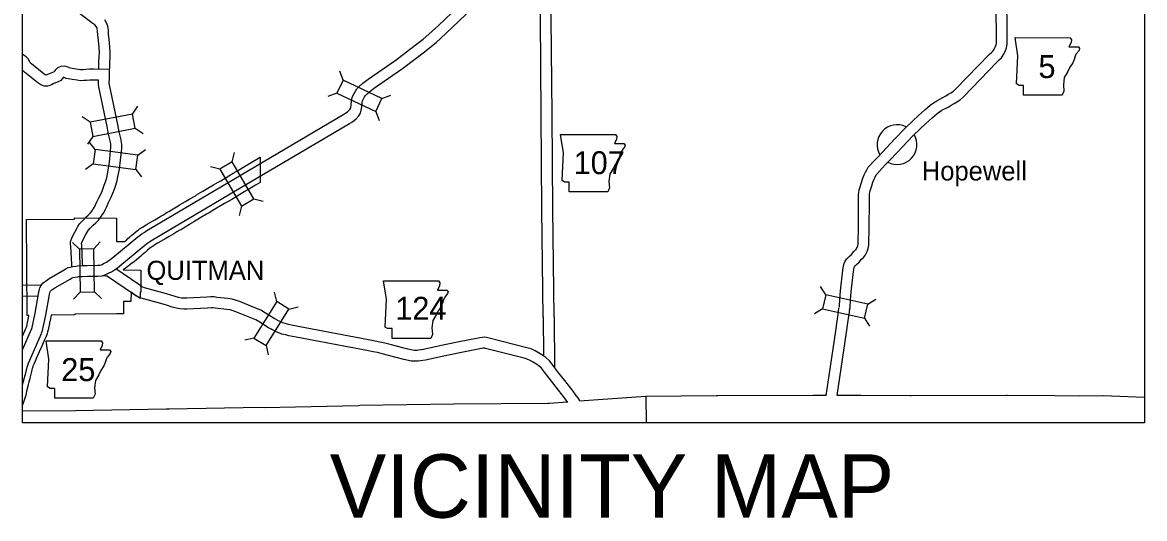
# Model space of a CAD drawing. Extents: x 1212896 to 1368412, y 378476 to 478763.
# Drawn here: x 1215273 to 1246287, y 442963 to 456675 of the extents above; entities that cross this region are included whole.
import ezdxf

# ---------------------------------------------------------------- set-up
doc = ezdxf.new("R2010")
doc.units = 0
for name, color, linetype in [('1', 7, 'Continuous'), ('2', 7, 'Continuous'), ('Level 10', 7, 'Continuous'), ('Level 11', 7, 'Continuous'), ('Level 2', 7, 'Continuous'), ('Level 20', 7, 'Continuous'), ('Level 21', 7, 'Continuous'), ('Level 24', 7, 'Continuous'), ('Level 6', 7, 'Continuous')]:
    doc.layers.add(name, color=color, linetype=linetype)

msp = doc.modelspace()

# ---------------------------------------------------------------- linework, layer by layer
at = {"layer": '1'}
msp.add_lwpolyline([(1215273, 477661), (1246287, 477661), (1246287, 445613), (1215273, 445613)], close=True, dxfattribs=at)
at = {"layer": 'Level 10'}
for points in [[(1237843, 448801), (1237852, 448843), (1237864, 449022), (1237881, 449261), (1237943, 449828), (1237954, 449896), (1237962, 449951), (1237983, 450013), (1238012, 450075), (1238058, 450141), (1238118, 450203), (1238184, 450264), (1238253, 450340), (1238302, 450386), (1238317, 450403), (1238329, 450423), (1238343, 450456), (1238358, 450499), (1238367, 450551), (1238378, 451043), (1238381, 451679), (1238382, 451902), (1238387, 451972), (1238400, 452047), (1238419, 452107), (1238461, 452252), (1238500, 452369), (1238540, 452465), (1238574, 452535), (1238610, 452605), (1238652, 452675), (1238820, 452858), (1238925, 452963), (1239047, 453092), (1239389, 453455), (1239657, 453739), (1239887, 453962), (1240034, 454092), (1240133, 454184), (1240215, 454259), (1240285, 454321), (1240363, 454388), (1240452, 454456), (1240541, 454508), (1240709, 454599), (1240796, 454650), (1240870, 454690), (1240936, 454732), (1241003, 454777), (1241081, 454846), (1241991, 455788), (1242062, 455855), (1242100, 455893), (1242132, 455939), (1242160, 455996), (1242183, 456055), (1242193, 456103), (1242193, 456181), (1242168, 459007)], [(1238135, 448735), (1238150, 448800), (1238163, 449001), (1238180, 449234), (1238240, 449788), (1238250, 449849), (1238255, 449880), (1238262, 449902), (1238272, 449925), (1238289, 449949), (1238328, 449988), (1238397, 450053), (1238467, 450129), (1238516, 450176), (1238560, 450225), (1238597, 450286), (1238623, 450347), (1238650, 450425), (1238666, 450522), (1238678, 451039), (1238681, 451677), (1238682, 451892), (1238685, 451936), (1238692, 451976), (1238706, 452021), (1238748, 452163), (1238781, 452264), (1238814, 452341), (1238842, 452401), (1238872, 452459), (1238894, 452495), (1239037, 452651), (1239140, 452754), (1239265, 452885), (1239607, 453249), (1239871, 453529), (1240091, 453742), (1240236, 453870), (1240337, 453964), (1240415, 454036), (1240482, 454095), (1240552, 454155), (1240619, 454206), (1240688, 454247), (1240856, 454337), (1240944, 454388), (1241023, 454432), (1241099, 454481), (1241187, 454539), (1241289, 454630), (1242202, 455574), (1242271, 455639), (1242332, 455700), (1242390, 455786), (1242435, 455875), (1242471, 455969), (1242494, 456071), (1242493, 456183), (1242467, 459015)], [(1215520, 448185), (1215540, 448241), (1215621, 448639), (1215730, 449216), (1215740, 449268), (1215755, 449341), (1215803, 449425), (1215848, 449474), (1215901, 449519), (1216012, 449596), (1216430, 449835), (1216473, 449866), (1216533, 449898), (1216596, 449915), (1216670, 449931), (1216746, 449940), (1216792, 449952), (1216915, 449954), (1217059, 449960), (1217348, 449966), (1217423, 449971), (1217454, 449979), (1217489, 449994), (1217536, 450018), (1217581, 450041), (1217651, 450086), (1217702, 450123), (1217769, 450181), (1218464, 450749), (1218526, 450800), (1218576, 450831), (1218633, 450869), (1218715, 450921), (1221112, 452344), (1224160, 454143), (1224215, 454175), (1224256, 454203), (1224288, 454230), (1224325, 454271), (1224338, 454292), (1224347, 454322), (1224358, 454381), (1224367, 454539), (1224400, 454625), (1224441, 454713), (1224474, 454773), (1224519, 454840), (1224588, 454918), (1224677, 454994), (1224832, 455111), (1225599, 455644), (1225971, 455924), (1226204, 456101), (1226345, 456216), (1226508, 456350), (1226770, 456592), (1227504, 457284)], [(1215803, 448085), (1215829, 448160), (1215916, 448581), (1216024, 449158), (1216034, 449208), (1216040, 449234), (1216047, 449247), (1216056, 449258), (1216084, 449281), (1216172, 449341), (1216591, 449582), (1216630, 449610), (1216645, 449618), (1216668, 449624), (1216719, 449635), (1216801, 449644), (1216833, 449652), (1216924, 449655), (1217067, 449660), (1217361, 449666), (1217473, 449673), (1217553, 449695), (1217617, 449723), (1217673, 449751), (1217731, 449781), (1217821, 449838), (1217888, 449888), (1217961, 449950), (1218654, 450516), (1218703, 450556), (1218740, 450581), (1218796, 450618), (1218872, 450666), (1221265, 452086), (1224311, 453884), (1224375, 453921), (1224438, 453963), (1224498, 454014), (1224566, 454090), (1224613, 454167), (1224639, 454250), (1224656, 454345), (1224664, 454475), (1224676, 454508), (1224709, 454578), (1224731, 454617), (1224757, 454656), (1224799, 454704), (1224865, 454761), (1225008, 454868), (1225775, 455401), (1226152, 455685), (1226390, 455866), (1226535, 455984), (1226705, 456124), (1226974, 456372), (1227711, 457067)], [(1217384, 455383), (1217388, 455580), (1217396, 455736), (1217401, 455840), (1217391, 455978), (1217373, 456175), (1217356, 456333), (1217349, 456430), (1217340, 456503), (1217328, 456536), (1217310, 456565), (1217272, 456606), (1217189, 456664), (1216659, 457071)], [(1216942, 449953), (1216933, 450016), (1216911, 450520), (1216905, 450569), (1216904, 450576), (1216905, 450579), (1216912, 450596), (1216931, 450640), (1217037, 450834), (1217064, 450881), (1217092, 450926), (1217149, 450990), (1217232, 451072), (1217301, 451135), (1217378, 451214), (1217434, 451288), (1217478, 451355), (1217520, 451415), (1217562, 451499), (1217607, 451592), (1217653, 451703), (1217728, 451846), (1217770, 451958), (1217814, 452064), (1217857, 452177), (1217894, 452310), (1217940, 452537), (1217954, 452620), (1217964, 452712), (1217974, 452787), (1217984, 452865), (1218008, 453099), (1218016, 453209), (1218022, 453297), (1218013, 453356), (1217999, 453431), (1217946, 453653), (1217927, 453749), (1217906, 453855), (1217683, 454954), (1217674, 455001), (1217673, 455026), (1217679, 455111), (1217681, 455226), (1217688, 455569), (1217696, 455721), (1217701, 455844), (1217690, 456002), (1217672, 456205), (1217654, 456359), (1217648, 456460), (1217633, 456571), (1217601, 456665), (1217549, 456749)], [(1216642, 449927), (1216634, 449989), (1216611, 450495), (1216605, 450547), (1216604, 450608), (1216618, 450666), (1216634, 450709), (1216662, 450773), (1216775, 450980), (1216807, 451035), (1216852, 451107), (1216931, 451196), (1217025, 451290), (1217092, 451351), (1217150, 451410), (1217189, 451461), (1217230, 451523), (1217261, 451569), (1217293, 451631), (1217333, 451714), (1217381, 451830), (1217454, 451969), (1217492, 452069), (1217535, 452174), (1217571, 452271), (1217602, 452380), (1217645, 452591), (1217656, 452660), (1217666, 452748), (1217676, 452826), (1217686, 452901), (1217709, 453125), (1217716, 453230), (1217720, 453286), (1217717, 453307), (1217706, 453368), (1217653, 453589), (1217632, 453692), (1217612, 453797), (1217389, 454896), (1217376, 454965), (1217373, 455028), (1217376, 455082)], [(1215273, 449413), (1215801, 449423), (1215805, 449424)], [(1215273, 449113), (1215709, 449121)], [(1237486, 446362), (1237681, 447650), (1237754, 448151), (1237791, 448420), (1237821, 448599), (1237832, 448689), (1237839, 448780)], [(1237789, 446363), (1237977, 447606), (1238051, 448109), (1238088, 448375), (1238117, 448556), (1238131, 448658), (1238139, 448756)], [(1215273, 447623), (1215524, 448195)], [(1215273, 446656), (1215372, 447032), (1215401, 447144), (1215419, 447202), (1215444, 447261), (1215477, 447340), (1215799, 448075)]]:
    msp.add_lwpolyline(points, dxfattribs=at)
at = {"layer": 'Level 11'}
for points in [[(1229668, 448533), (1229628, 451503), (1229614, 454125), (1229588, 456789), (1229582, 457913), (1229578, 457942)], [(1229968, 448537), (1229928, 451506), (1229914, 454127), (1229888, 456791), (1229882, 457934), (1229873, 458001), (1229863, 458053)], [(1217673, 455377), (1217238, 455384), (1217123, 455380), (1217023, 455373), (1216951, 455369), (1216882, 455366), (1216826, 455372), (1216706, 455393), (1216605, 455413), (1216566, 455420), (1216552, 455425), (1216507, 455447), (1216435, 455465), (1216338, 455461), (1216238, 455421), (1216181, 455355), (1216154, 455316), (1216146, 455312), (1216009, 455252), (1215950, 455228), (1215923, 455215), (1215875, 455249), (1215526, 455527), (1215497, 455553), (1215489, 455563), (1215479, 455586), (1215431, 455670), (1215372, 455723), (1215320, 455758), (1215294, 455780), (1215283, 455792), (1215273, 455807)], [(1217375, 455082), (1217241, 455084), (1217137, 455080), (1217043, 455074), (1216967, 455069), (1216872, 455065), (1216783, 455075), (1216651, 455098), (1216550, 455118), (1216481, 455130), (1216430, 455151), (1216411, 455160), (1216385, 455123), (1216338, 455074), (1216276, 455041), (1216125, 454976), (1216074, 454955), (1216030, 454933), (1215963, 454909), (1215874, 454909), (1215777, 454951), (1215695, 455009), (1215333, 455298), (1215280, 455344), (1215273, 455353)], [(1222365, 448421), (1222229, 448494), (1221992, 448642), (1221860, 448723), (1221653, 448810), (1221278, 448960), (1221166, 449003), (1221072, 449027), (1220952, 449041), (1220642, 449077), (1220573, 449088), (1220482, 449089), (1220372, 449080), (1219815, 449051), (1219751, 449052), (1219669, 449059), (1219588, 449075), (1219490, 449099), (1219376, 449133), (1219254, 449177), (1218645, 449343), (1218601, 449357), (1218563, 449376), (1218488, 449428), (1217851, 449865)], [(1222222, 448157), (1222078, 448235), (1221834, 448387), (1221722, 448456), (1221539, 448532), (1221168, 448681), (1221074, 448717), (1221017, 448732), (1220918, 448743), (1220602, 448780), (1220549, 448788), (1220494, 448788), (1220392, 448780), (1219820, 448751), (1219736, 448752), (1219627, 448761), (1219523, 448782), (1219412, 448809), (1219282, 448848), (1219164, 448891), (1218559, 449055), (1218487, 449078), (1218410, 449117), (1218318, 449181), (1217628, 449654), (1217621, 449658), (1217612, 449661), (1217577, 449667), (1217522, 449672), (1217483, 449672)], [(1229668, 448534), (1229674, 447468)], [(1229968, 448536), (1229976, 447128)], [(1230345, 446173), (1230251, 446304), (1230025, 446592), (1229828, 446848), (1229704, 447007), (1229618, 447119), (1229549, 447183), (1229467, 447240), (1229390, 447288), (1229310, 447330), (1229225, 447368), (1229136, 447396), (1228075, 447666), (1228055, 447669), (1228036, 447672), (1228011, 447670), (1227963, 447664), (1227358, 447547), (1226876, 447444), (1226413, 447343), (1226275, 447321), (1226212, 447313), (1226153, 447309), (1226094, 447309), (1226013, 447317), (1225942, 447332), (1225818, 447362), (1225394, 447470), (1225211, 447518), (1225089, 447549), (1224963, 447575), (1224788, 447604), (1222842, 447976), (1222640, 448013), (1222549, 448037), (1222446, 448064), (1222359, 448094), (1222287, 448125), (1222221, 448157), (1222160, 448194)], [(1230589, 446348), (1230491, 446483), (1230262, 446776), (1230065, 447031), (1229941, 447191), (1229840, 447322), (1229739, 447416), (1229632, 447491), (1229539, 447548), (1229441, 447600), (1229330, 447650), (1229217, 447684), (1228135, 447961), (1228096, 447966), (1228048, 447972), (1227983, 447969), (1227913, 447960), (1227298, 447841), (1226812, 447737), (1226358, 447638), (1226232, 447618), (1226184, 447611), (1226143, 447609), (1226109, 447609), (1226059, 447614), (1226008, 447625), (1225890, 447653), (1225469, 447761), (1225285, 447809), (1225155, 447841), (1225018, 447870), (1224841, 447899), (1222898, 448270), (1222706, 448306), (1222626, 448327), (1222534, 448351), (1222467, 448374), (1222411, 448399), (1222365, 448421), (1222315, 448451)], [(1230682, 446213), (1230673, 446233), (1230641, 446285), (1230599, 446344), (1230564, 446374)]]:
    msp.add_lwpolyline(points, dxfattribs=at)
at = {"layer": 'Level 2'}
for points in [[(1237486, 446362), (1237171, 446361), (1237127, 446361), (1234489, 446356), (1234455, 446352), (1232501, 446341), (1231183, 446246), (1230674, 446207)], [(1232501, 446341), (1232510, 445613)], [(1246287, 446307), (1245146, 446354), (1245137, 446354), (1244476, 446350), (1243807, 446353), (1242485, 446361), (1242461, 446362), (1239833, 446359), (1239805, 446357), (1238444, 446366), (1237789, 446363)], [(1230334, 446181), (1229832, 446140), (1229805, 446141), (1227200, 446129), (1224599, 446084), (1224557, 446083), (1221954, 446028), (1221885, 446029), (1219333, 445986), (1219243, 445983), (1216736, 445937), (1215273, 445929)]]:
    msp.add_lwpolyline(points, dxfattribs=at)
at = {"layer": 'Level 20'}
for p, q in [((1224133, 455080), (1224043, 455328)), ((1224133, 455080), (1223965, 454721)), ((1225208, 454575), (1224133, 455080)), ((1223965, 454721), (1223716, 454631)), ((1223965, 454721), (1225040, 454216)), ((1225208, 454575), (1225457, 454664)), ((1218312, 454142), (1218460, 454361)), ((1225040, 454216), (1225208, 454575)), ((1217146, 453916), (1216927, 454063)), ((1218312, 454142), (1217146, 453916)), ((1218388, 453754), (1218312, 454142)), ((1225040, 454216), (1225130, 453968)), ((1217146, 453916), (1217222, 453527)), ((1217222, 453527), (1218388, 453754)), ((1218388, 453754), (1218607, 453606)), ((1217222, 453527), (1217074, 453308)), ((1217282, 453163), (1217122, 453373)), ((1217282, 453163), (1217230, 452771)), ((1218460, 453007), (1217282, 453163)), ((1218460, 453007), (1218670, 453167)), ((1218408, 452614), (1218460, 453007)), ((1221066, 452823), (1220726, 452621)), ((1221066, 452823), (1221132, 453079)), ((1221673, 451801), (1221066, 452823)), ((1217230, 452771), (1217020, 452610)), ((1217230, 452771), (1218408, 452614)), ((1218408, 452614), (1218568, 452405)), ((1220726, 452621), (1220470, 452686)), ((1220726, 452621), (1221332, 451599)), ((1221332, 451599), (1221267, 451343)), ((1221332, 451599), (1221673, 451801)), ((1221673, 451801), (1221929, 451736)), ((1216846, 450409), (1216656, 450592)), ((1217242, 450417), (1216846, 450409)), ((1216846, 450409), (1216870, 449221)), ((1217242, 450417), (1217425, 450607)), ((1217266, 449229), (1217242, 450417)), ((1216870, 449221), (1216687, 449031)), ((1216870, 449221), (1217266, 449229)), ((1217266, 449229), (1217456, 449046)), ((1222300, 448962), (1222240, 449219)), ((1237475, 449150), (1237334, 449373)), ((1237475, 449150), (1237389, 448763)), ((1238634, 448889), (1237475, 449150)), ((1222300, 448962), (1221673, 447953)), ((1222636, 448753), (1222300, 448962)), ((1222636, 448753), (1222893, 448813)), ((1238548, 448503), (1238634, 448889)), ((1238634, 448889), (1238857, 449031)), ((1222009, 447744), (1222636, 448753)), ((1237389, 448763), (1237166, 448622)), ((1237389, 448763), (1238548, 448503)), ((1238548, 448503), (1238689, 448280)), ((1221673, 447953), (1221416, 447893)), ((1221673, 447953), (1222009, 447744)), ((1222009, 447744), (1222069, 447487))]:
    msp.add_line(p, q, dxfattribs=at)
at = {"layer": 'Level 21'}
for p, q in [((1242783, 455748), (1242707, 456255)), ((1242707, 456255), (1244228, 456254)), ((1244228, 456254), (1244263, 456196)), ((1244229, 456255), (1244229, 456255)), ((1244255, 456120), (1244196, 456001)), ((1244196, 456001), (1244458, 456001)), ((1244263, 456196), (1244255, 456120)), ((1244475, 455900), (1244399, 455807)), ((1244458, 456001), (1244492, 455959)), ((1244492, 455959), (1244475, 455900)), ((1242749, 454978), (1242783, 455748)), ((1244356, 455697), (1244306, 455561)), ((1244356, 455697), (1244399, 455807)), ((1244162, 455316), (1244069, 455155)), ((1244221, 455435), (1244162, 455316)), ((1244306, 455561), (1244221, 455435)), ((1242817, 454935), (1242749, 454978)), ((1244069, 455155), (1244043, 454952)), ((1242944, 454935), (1242817, 454935)), ((1242944, 454665), (1242944, 454935)), ((1244010, 454665), (1242944, 454665)), ((1244060, 454775), (1244010, 454665)), ((1244043, 454952), (1244060, 454775)), ((1230224, 453074), (1230148, 453581)), ((1230148, 453581), (1231669, 453580)), ((1231696, 453446), (1231637, 453327)), ((1231669, 453580), (1231704, 453522)), ((1231670, 453581), (1231670, 453581)), ((1231704, 453522), (1231696, 453446)), ((1231637, 453327), (1231899, 453327)), ((1231797, 453023), (1231840, 453133)), ((1231916, 453226), (1231840, 453133)), ((1231899, 453327), (1231933, 453285)), ((1231933, 453285), (1231916, 453226)), ((1230190, 452304), (1230224, 453074)), ((1231747, 452887), (1231662, 452761)), ((1231797, 453023), (1231747, 452887)), ((1231603, 452642), (1231510, 452481)), ((1231662, 452761), (1231603, 452642)), ((1230258, 452262), (1230190, 452304)), ((1230385, 452262), (1230258, 452262)), ((1230385, 451991), (1230385, 452262)), ((1231510, 452481), (1231484, 452278)), ((1231484, 452278), (1231501, 452101)), ((1231450, 451991), (1230385, 451991)), ((1231501, 452101), (1231450, 451991)), ((1225331, 449027), (1225255, 449534)), ((1225255, 449534), (1226777, 449533)), ((1226803, 449399), (1226744, 449280)), ((1226777, 449533), (1226812, 449475)), ((1226778, 449534), (1226778, 449534)), ((1226812, 449475), (1226803, 449399)), ((1226744, 449280), (1227006, 449280)), ((1226905, 448976), (1226947, 449086)), ((1227023, 449179), (1226947, 449086)), ((1227006, 449280), (1227040, 449238)), ((1227040, 449238), (1227023, 449179)), ((1225298, 448257), (1225331, 449027)), ((1226854, 448840), (1226769, 448714)), ((1226905, 448976), (1226854, 448840)), ((1226710, 448595), (1226617, 448434)), ((1226769, 448714), (1226710, 448595)), ((1225365, 448214), (1225298, 448257)), ((1225492, 448214), (1225365, 448214)), ((1225492, 447944), (1225492, 448214)), ((1226617, 448434), (1226592, 448231)), ((1226592, 448231), (1226609, 448054)), ((1216004, 447371), (1215928, 447879)), ((1215928, 447879), (1217450, 447878)), ((1217450, 447878), (1217485, 447819)), ((1217451, 447879), (1217451, 447879)), ((1226558, 447944), (1225492, 447944)), ((1226609, 448054), (1226558, 447944)), ((1217476, 447743), (1217417, 447625)), ((1217417, 447625), (1217679, 447625)), ((1217485, 447819), (1217476, 447743)), ((1217696, 447523), (1217620, 447430)), ((1217679, 447625), (1217713, 447583)), ((1217713, 447583), (1217696, 447523)), ((1215970, 446601), (1216004, 447371)), ((1217578, 447320), (1217527, 447185)), ((1217578, 447320), (1217620, 447430)), ((1217383, 446940), (1217290, 446779)), ((1217442, 447058), (1217383, 446940)), ((1217527, 447185), (1217442, 447058)), ((1216038, 446559), (1215970, 446601)), ((1217290, 446779), (1217265, 446576)), ((1216165, 446559), (1216038, 446559)), ((1216165, 446288), (1216165, 446559)), ((1217231, 446288), (1216165, 446288)), ((1217282, 446398), (1217231, 446288)), ((1217265, 446576), (1217282, 446398))]:
    msp.add_line(p, q, dxfattribs=at)
at = {"layer": 'Level 24'}
for start, end in [(63.47, 210.9797), (242.6713, 30.5656)]:
    msp.add_arc((1239444, 453298), 550, start, end, dxfattribs=at)
at = {"layer": 'Level 6'}
for points in [[(1220258, 452009), (1220354, 452065), (1220556, 452186), (1220679, 452257), (1220752, 452300), (1220876, 452375), (1220975, 452433), (1221096, 452505), (1221183, 452556), (1221246, 452593), (1221408, 452689), (1221504, 452747), (1221843, 452948)], [(1221843, 452948), (1221844, 452251)], [(1221844, 452251), (1221715, 452174), (1221550, 452075), (1221485, 452038), (1221401, 451989), (1221280, 451916), (1221182, 451859), (1221058, 451784), (1220981, 451739), (1220861, 451669), (1220658, 451548), (1220562, 451492)], [(1218095, 450620), (1218146, 450662), (1218172, 450687), (1218242, 450748), (1218272, 450775), (1218294, 450792), (1218339, 450832), (1218418, 450900), (1218451, 450925), (1218477, 450944), (1218507, 450967), (1218531, 450983), (1218547, 450993), (1218564, 451003), (1218571, 451007), (1218587, 451018), (1218606, 451030), (1218647, 451055), (1218695, 451084), (1218718, 451098), (1218781, 451135), (1218928, 451222), (1219025, 451279), (1219097, 451321), (1219150, 451351), (1219236, 451403), (1219277, 451427), (1219316, 451449), (1219347, 451466), (1219573, 451603), (1219603, 451622), (1219634, 451640), (1219698, 451679), (1219781, 451728), (1219811, 451745), (1219902, 451797), (1220053, 451887), (1220075, 451901), (1220094, 451912), (1220116, 451925), (1220133, 451935), (1220258, 452009)], [(1216715, 451237), (1216714, 451279), (1217871, 451270), (1217874, 450619), (1218095, 450620)], [(1220562, 451492), (1220434, 451416), (1220414, 451404), (1220397, 451394), (1220383, 451386), (1220362, 451373), (1220207, 451280), (1220106, 451222), (1220080, 451207), (1220006, 451164), (1219942, 451125), (1219917, 451110), (1219888, 451092), (1219648, 450947), (1219608, 450925), (1219576, 450907), (1219543, 450888), (1219454, 450834), (1219396, 450800), (1219328, 450761), (1219234, 450705), (1219086, 450618), (1219025, 450582), (1219005, 450570), (1218961, 450544), (1218923, 450520), (1218907, 450510), (1218884, 450495), (1218873, 450489), (1218864, 450484), (1218857, 450479), (1218853, 450476), (1218836, 450464), (1218813, 450447), (1218795, 450432), (1218732, 450379), (1218683, 450335), (1218664, 450320), (1218639, 450298), (1218574, 450242), (1218544, 450213), (1218429, 450117), (1218357, 450062), (1218291, 450012), (1218253, 449984), (1218184, 449932), (1218145, 449902), (1218055, 449833)], [(1215451, 448575), (1215402, 448575), (1215387, 451226), (1216715, 451237)], [(1218055, 449833), (1218549, 449830), (1218548, 449219)], [(1218274, 449229), (1218272, 448964), (1218065, 448963), (1218062, 448624), (1217885, 448623), (1216724, 448616), (1216725, 448591), (1216063, 448581)], [(1218527, 449042), (1218505, 449061), (1218490, 449073), (1218390, 449140), (1218362, 449160), (1218315, 449196), (1218274, 449229)], [(1218548, 449219), (1218543, 449221), (1218538, 449223), (1218527, 449229), (1218525, 449230)], [(1218525, 449230), (1218527, 449042)], [(1216063, 448581), (1216055, 448543), (1216045, 448485), (1216027, 448396), (1216025, 448385), (1216021, 448355), (1216013, 448312), (1216005, 448272), (1215985, 448178), (1215970, 448122), (1215954, 448066), (1215938, 448020), (1215910, 447955), (1215887, 447904), (1215850, 447822), (1215806, 447725), (1215735, 447567), (1215662, 447404), (1215621, 447312), (1215593, 447250), (1215573, 447197), (1215564, 447173), (1215559, 447160), (1215550, 447132), (1215543, 447111), (1215534, 447073), (1215523, 447027), (1215486, 446884), (1215473, 446827), (1215453, 446744), (1215449, 446727), (1215445, 446707), (1215435, 446665), (1215423, 446618), (1215390, 446485), (1215363, 446374), (1215331, 446262), (1215304, 446182), (1215282, 446129), (1215273, 446109)], [(1215273, 448003), (1215303, 448069), (1215341, 448152), (1215361, 448197), (1215378, 448237), (1215383, 448251), (1215392, 448282), (1215401, 448317), (1215417, 448390), (1215423, 448423), (1215429, 448456), (1215433, 448481), (1215437, 448504), (1215451, 448575)]]:
    msp.add_lwpolyline(points, dxfattribs=at)

# ---------------------------------------------------------------- texts
at = {"layer": '2'}
msp.add_text('VICINITY MAP', height=1750, dxfattribs=at).set_placement((1223767, 442988))
at = {"layer": 'Level 21'}
for s, height, p in [('5', 634, (1243354, 455138)), ('107', 633.6, (1230507, 452482)), ('124', 633.6, (1225578, 448458)), ('25', 633.6, (1216346, 446763))]:
    msp.add_text(s, height=height, dxfattribs=at).set_placement(p)
at = {"layer": 'Level 24'}
msp.add_text('Hopewell', height=528, dxfattribs=at).set_placement((1240130, 452307))
at = {"layer": 'Level 6'}
msp.add_text('QUITMAN', height=528, dxfattribs=at).set_placement((1218702, 449560))

doc.saveas('drawing.dxf')
